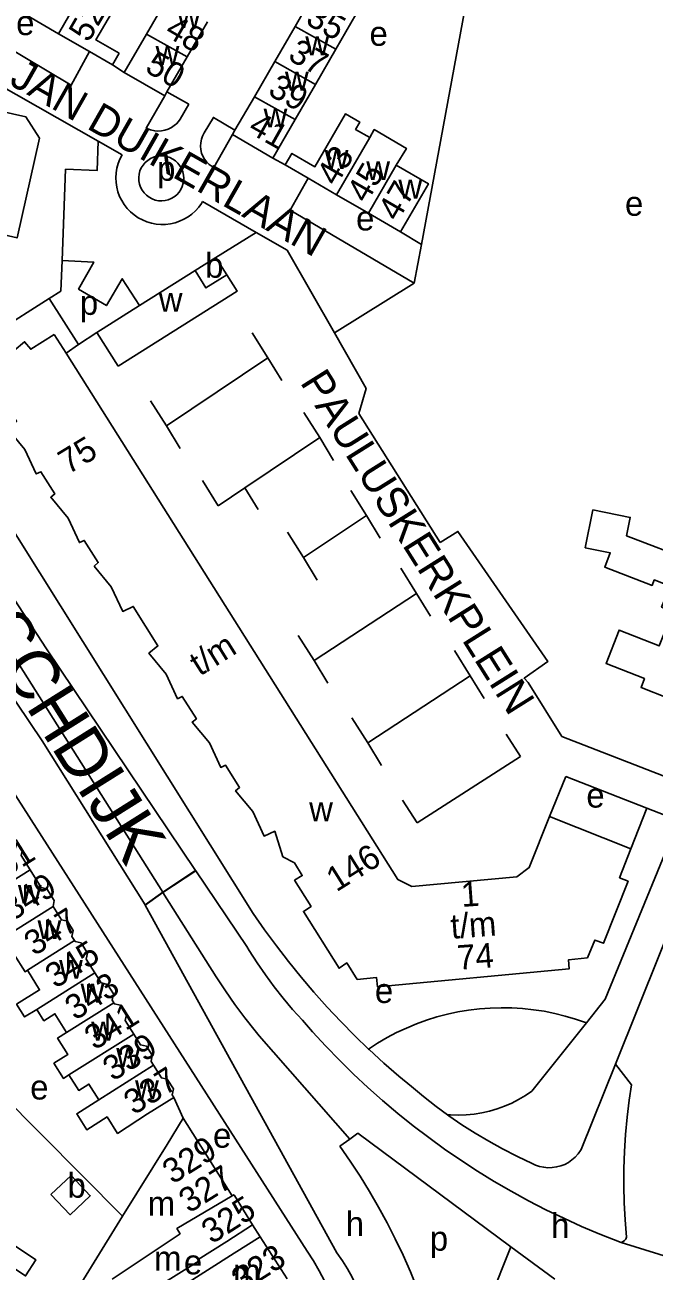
# Model space of a CAD drawing. Extents: x 159294 to 161936, y 384538 to 386517.
# Drawn here: x 160269 to 160371.2, y 384817.5 to 385020 of the extents above; entities that cross this region are included whole.
import ezdxf

# ---------------------------------------------------------------- set-up
doc = ezdxf.new("R2010")
doc.units = 0
for name, color, linetype in [('BLT_Basislijn', 7, 'Continuous'), ('BLT_Bebouwing', 7, 'Continuous'), ('BLT_Centroide', 7, 'Continuous'), ('BLT_Huisnummer', 7, 'Continuous'), ('BLT_Huisnummer_ tussenligend', 7, 'Continuous'), ('BLT_Huisnummer_reeks', 7, 'Continuous'), ('BLT_Onderverdeling_panden', 7, 'Continuous'), ('BLT_Straatnaam', 7, 'Continuous'), ('BLT_Straatnaam_hoofdweg', 7, 'Continuous'), ('BLT_Vlakafsluiter', 7, 'Continuous')]:
    doc.layers.add(name, color=color, linetype=linetype)

msp = doc.modelspace()

# ---------------------------------------------------------------- linework, layer by layer
at = {"layer": 'BLT_Basislijn'}
for p, q in [((160341.25, 385026.66), (160333.43, 384984.3)), ((160280.91, 385001.11), (160257.3, 385014.58)), ((160283.25, 385013.53), (160285.16, 385012.29)), ((160291.73, 385008.49), (160288.71, 385003.24)), ((160292.09, 385009.11), (160295.65, 385007.12)), ((160295.65, 385007.12), (160294.23, 385004.67)), ((160302.75, 385002.2), (160299.69, 384996.83)), ((160284.8, 384998.89), (160280.91, 385001.11)), ((160311.31, 384997.24), (160309.3, 384998.34)), ((160297.9, 384991.3), (160306.57, 384986.29)), ((160300.06, 384982.22), (160306.57, 384986.29)), ((160306.57, 384986.29), (160311.62, 384983.38)), ((160330.06, 384986.36), (160333.43, 384984.3)), ((160311.62, 384983.38), (160319.31, 384969.96)), ((160333.43, 384984.3), (160332.27, 384978.05)), ((160332.27, 384978.05), (160319.31, 384969.96)), ((160272.95, 384975.52), (160251.85, 384962.2)), ((160272.95, 384975.52), (160277.71, 384968.07)), ((160280.7, 384970.01), (160277.71, 384968.07)), ((160305.94, 384969.98), (160308.5, 384965.9)), ((160277.71, 384968.07), (160275.72, 384966.65)), ((160292, 384954.84), (160308.5, 384965.9)), ((160308.5, 384965.9), (160310.74, 384962.21)), ((160306.11, 384875.6), (160251.85, 384962.2)), ((160289.44, 384958.93), (160292, 384954.84)), ((160314.35, 384957), (160316.91, 384952.92)), ((160336.47, 384935.87), (160323.29, 384956.87)), ((160292, 384954.84), (160294.24, 384951.15)), ((160304.74, 384944.76), (160316.91, 384952.92)), ((160316.91, 384952.92), (160319.15, 384949.23)), ((160297.85, 384945.95), (160300.41, 384941.86)), ((160300.41, 384941.86), (160304.74, 384944.76)), ((160304.74, 384944.76), (160306.9, 384941.22)), ((160321.95, 384944.34), (160324.52, 384940.26)), ((160314.27, 384933.44), (160324.52, 384940.26)), ((160324.52, 384940.26), (160326.76, 384936.57)), ((160311.7, 384937.53), (160314.27, 384933.44)), ((160314.27, 384933.44), (160316.51, 384929.76)), ((160330.09, 384931.68), (160332.65, 384927.59)), ((160315.99, 384916.69), (160332.65, 384927.59)), ((160332.65, 384927.59), (160334.89, 384923.9)), ((160313.43, 384920.78), (160315.99, 384916.69)), ((160266.83, 384917.98), (160291.41, 384879.02)), ((160315.99, 384916.69), (160318.24, 384913.01)), ((160338.82, 384918.3), (160341.38, 384914.21)), ((160324.72, 384903.31), (160341.38, 384914.21)), ((160341.38, 384914.21), (160343.62, 384910.52)), ((160356.27, 384904.35), (160350.76, 384913.11)), ((160322.16, 384907.4), (160324.72, 384903.31)), ((160260.57, 384905.54), (160314.88, 384820.71)), ((160347.2, 384904.75), (160349.55, 384901.07)), ((160356.27, 384904.35), (160373.69, 384897.57)), ((160324.72, 384903.31), (160326.97, 384899.62)), ((160332.73, 384890.33), (160349.55, 384901.07)), ((160354.25, 384891.33), (160356.88, 384897.86)), ((160370.03, 384892.72), (160356.88, 384897.86)), ((160330.38, 384894.01), (160332.73, 384890.33)), ((160367.44, 384886.09), (160370.03, 384892.72)), ((160375.22, 384890.69), (160370.03, 384892.72)), ((160363.31, 384861.65), (160375.22, 384890.69)), ((160364.96, 384851.1), (160380.05, 384888.81)), ((160305.07, 384870.21), (160296.79, 384882.51)), ((160291.41, 384879.02), (160291.44, 384878.98)), ((160300.12, 384865.26), (160291.44, 384878.98)), ((160319.7, 384820.42), (160288.58, 384876.95)), ((160360.23, 384857.8), (160363.31, 384861.65)), ((160351.39, 384846.7), (160360.23, 384857.8)), ((160307.06, 384855.7), (160321.82, 384838.92)), ((160359.4, 384837.21), (160364.96, 384851.1)), ((160367.56, 384847.72), (160364.96, 384851.1)), ((160293.19, 384845.67), (160294.74, 384842.3)), ((160321.82, 384838.92), (160323.11, 384839.87)), ((160347.95, 384821.42), (160323.11, 384839.87)), ((160320.2, 384837.74), (160321.82, 384838.92)), ((160349.16, 384836), (160351.34, 384834.97)), ((160307.25, 384823.03), (160306.02, 384824.96)), ((160340.25, 384802.05), (160347.95, 384821.42)), ((160355.09, 384816.13), (160347.95, 384821.42))]:
    msp.add_line(p, q, dxfattribs=at)
for points in [[(160169.35, 385059.37), (160171.25, 385060.52), (160174.16, 385057.66), (160190.75, 385031.46), (160212.88, 384996.72), (160224.1, 384978.45), (160234.05, 384962.08), (160257.3, 384925.15), (160271.83, 384903.65), (160288.55, 384876.99)], [(160296.76, 384882.55), (160272.55, 384918.59), (160254.52, 384946.2), (160219.9, 385000), (160208.49, 385023.25)], [(160279.53, 385015.66), (160276.53, 385010.22), (160261.44, 385019.19)], [(160294.23, 385004.67), (160293.95, 385004.28), (160293.63, 385003.92), (160293.27, 385003.63), (160292.85, 385003.34), (160292.31, 385003.07), (160291.78, 385002.88), (160291.21, 385002.78), (160290.61, 385002.73), (160290.11, 385002.77), (160289.41, 385002.93), (160288.97, 385003.11), (160288.71, 385003.24)], [(160303.14, 385002.88), (160299.65, 385004.97), (160298.13, 385002.44)], [(160298.13, 385002.44), (160297.87, 385001.94), (160297.69, 385001.41), (160297.58, 385000.85), (160297.55, 385000.29), (160297.6, 384999.73), (160297.73, 384999.18), (160297.94, 384998.65), (160298.21, 384998.16), (160298.56, 384997.71), (160298.96, 384997.32), (160299.42, 384996.99), (160299.69, 384996.83)], [(160280.91, 385001.11), (160280.76, 384996.32), (160275.63, 384996.54), (160275.05, 384981.72)], [(160284.8, 384998.89), (160284.44, 384998.2), (160284.17, 384997.47), (160283.96, 384996.72), (160283.84, 384995.95), (160283.8, 384995.17), (160283.83, 384994.4), (160283.95, 384993.63), (160284.14, 384992.87), (160284.41, 384992.14), (160284.75, 384991.44), (160285.16, 384990.79), (160285.64, 384990.17), (160286.18, 384989.61), (160286.78, 384989.11), (160287.42, 384988.67), (160288.1, 384988.3), (160288.82, 384988), (160289.57, 384987.77), (160290.33, 384987.63), (160291.11, 384987.56), (160291.88, 384987.57), (160292.65, 384987.67), (160293.42, 384987.84), (160294.15, 384988.08), (160294.86, 384988.41), (160295.53, 384988.8), (160296.16, 384989.26), (160296.74, 384989.78), (160297.26, 384990.36), (160297.71, 384990.99), (160297.9, 384991.3)], [(160294.84, 384995.07), (160294.8, 384995.6), (160294.68, 384996.13), (160294.48, 384996.64), (160294.21, 384997.11), (160293.88, 384997.53), (160293.49, 384997.9), (160293.04, 384998.21), (160292.56, 384998.45), (160292.05, 384998.62), (160291.51, 384998.71), (160290.97, 384998.72), (160290.43, 384998.65), (160289.92, 384998.5), (160289.42, 384998.28), (160288.97, 384997.98), (160288.56, 384997.63), (160288.21, 384997.21), (160287.93, 384996.75), (160287.72, 384996.26), (160287.58, 384995.73), (160287.52, 384995.2), (160287.54, 384994.66), (160287.64, 384994.12), (160287.82, 384993.61), (160288.07, 384993.14), (160288.39, 384992.7), (160288.76, 384992.31), (160289.2, 384991.99), (160289.67, 384991.73), (160290.18, 384991.54), (160290.71, 384991.43), (160291.25, 384991.41), (160291.79, 384991.46), (160292.31, 384991.59), (160292.81, 384991.79), (160293.28, 384992.07), (160293.7, 384992.41), (160294.06, 384992.81), (160294.36, 384993.26), (160294.59, 384993.75), (160294.75, 384994.27), (160294.83, 384994.8), (160294.84, 384995.07)], [(160315.03, 384995.08), (160312.12, 384989.88), (160332.27, 384978.05)], [(160275.05, 384981.72), (160274.86, 384976.73), (160272.95, 384975.52)], [(160275.05, 384981.72), (160280.22, 384981.46), (160277.73, 384977.06), (160282.26, 384974.39), (160284.85, 384978.74), (160287.65, 384974.4)], [(160319.31, 384969.96), (160324.48, 384960.92), (160323.29, 384956.87)], [(160336.47, 384935.87), (160339.38, 384937.69), (160353.96, 384916.53), (160350.11, 384913.81), (160350.76, 384913.11)], [(160296.79, 384882.51), (160296.76, 384882.55)], [(160288.55, 384876.99), (160288.58, 384876.95)], [(160306.11, 384875.6), (160307.96, 384872.94), (160309.87, 384870.32), (160311.84, 384867.76), (160313.88, 384865.24), (160315.98, 384862.78), (160318.14, 384860.36), (160320.36, 384858), (160322.63, 384855.7), (160324.86, 384853.55)], [(160314.1, 384858.23), (160312.5, 384859.99), (160310.97, 384861.8), (160309.5, 384863.67), (160308.09, 384865.58), (160306.75, 384867.54), (160305.48, 384869.54), (160305.07, 384870.21)], [(160284.89, 384826.37), (160258.47, 384853), (160249.23, 384869.23)], [(160300.12, 384865.26), (160301.6, 384862.99), (160303.14, 384860.78), (160304.75, 384858.6), (160306.42, 384856.48), (160307.06, 384855.7)], [(160324.86, 384853.55), (160326.33, 384854.51), (160327.85, 384855.4), (160329.41, 384856.22), (160331, 384856.96), (160332.62, 384857.64), (160334.28, 384858.24), (160335.96, 384858.76), (160337.66, 384859.21), (160339.38, 384859.58), (160341.11, 384859.87), (160342.86, 384860.08), (160344.61, 384860.21), (160346.37, 384860.27), (160348.12, 384860.24), (160349.88, 384860.13), (160351.63, 384859.94), (160353.37, 384859.68), (160355.09, 384859.33), (160356.8, 384858.91), (160358.48, 384858.41), (160360.23, 384857.8)], [(160365.91, 384822.11), (160362.41, 384823.45), (160359.46, 384824.7), (160356.55, 384826.03), (160353.67, 384827.42), (160350.83, 384828.89), (160348.02, 384830.43), (160345.26, 384832.04), (160342.53, 384833.72), (160339.85, 384835.46), (160337.21, 384837.27), (160334.62, 384839.15), (160332.08, 384841.09), (160329.59, 384843.09), (160327.14, 384845.16), (160324.75, 384847.28), (160322.41, 384849.47), (160320.13, 384851.71), (160317.9, 384854.01), (160315.74, 384856.36), (160314.1, 384858.23)], [(160324.86, 384853.55), (160324.96, 384853.45), (160327.35, 384851.27), (160329.79, 384849.14), (160331.8, 384847.46)], [(160366.78, 384822.99), (160366.55, 384825.76), (160366.4, 384828.54), (160366.33, 384831.33), (160366.34, 384834.11), (160366.43, 384836.9), (160366.61, 384839.68), (160366.86, 384842.45), (160367.19, 384845.22), (160367.56, 384847.72)], [(160331.8, 384847.46), (160333.78, 384845.81), (160335.81, 384844.23), (160337.67, 384842.86)], [(160351.39, 384846.7), (160350.33, 384845.98), (160349.23, 384845.33), (160348.1, 384844.75), (160346.92, 384844.24), (160345.72, 384843.8), (160344.49, 384843.45), (160343.25, 384843.16), (160341.98, 384842.96), (160340.71, 384842.84), (160339.43, 384842.79), (160338.16, 384842.83), (160337.67, 384842.86)], [(160337.67, 384842.86), (160337.88, 384842.71), (160340.01, 384841.25), (160342.17, 384839.87), (160344.38, 384838.55), (160346.63, 384837.3), (160348.92, 384836.11), (160349.16, 384836)], [(160320.2, 384837.74), (160321.87, 384835.33), (160323.47, 384832.88), (160325.01, 384830.39), (160326.48, 384827.86), (160327.87, 384825.29), (160329.2, 384822.68), (160330.45, 384820.04), (160331.64, 384817.36), (160332.74, 384814.65), (160333.78, 384811.91), (160334.74, 384809.15), (160335.62, 384806.36), (160336.43, 384803.55), (160337.17, 384800.64)], [(160351.34, 384834.97), (160351.97, 384834.68), (160352.63, 384834.46), (160353.31, 384834.32), (160354, 384834.26), (160354.7, 384834.28), (160355.39, 384834.38), (160356.06, 384834.55), (160356.71, 384834.8), (160357.33, 384835.13), (160357.9, 384835.52), (160358.43, 384835.98), (160358.9, 384836.49), (160359.3, 384837.06), (160359.4, 384837.21)], [(160365.91, 384822.11), (160366.21, 384822.27), (160366.45, 384822.42), (160366.63, 384822.63), (160366.78, 384822.99)], [(160314.88, 384820.71), (160315.89, 384819.13), (160316.84, 384817.51), (160317.71, 384815.85), (160318.52, 384814.15), (160319.25, 384812.42), (160319.5, 384811.75)], [(160319.7, 384820.42), (160320.6, 384819.14), (160321.44, 384817.81), (160322.21, 384816.44), (160322.91, 384815.03), (160323.53, 384813.59), (160324.08, 384812.12), (160324.56, 384810.63), (160324.96, 384809.11), (160325.28, 384807.57), (160325.46, 384806.48)]]:
    msp.add_lwpolyline(points, dxfattribs=at)
at = {"layer": 'BLT_Bebouwing'}
for p, q in [((160292.08, 385024.23), (160288.77, 385018.52)), ((160312.91, 385019.77), (160316.23, 385025.5)), ((160274.49, 385018.58), (160269.4, 385021.52)), ((160295.38, 385014.79), (160298.7, 385020.5)), ((160309.61, 385014.06), (160312.91, 385019.77)), ((160279.53, 385015.66), (160274.49, 385018.58)), ((160288.77, 385018.52), (160285.16, 385012.29)), ((160283.25, 385013.53), (160279.53, 385015.66)), ((160319.53, 385016.04), (160316.23, 385010.33)), ((160284.33, 385015.42), (160283.25, 385013.53)), ((160292.09, 385009.11), (160295.38, 385014.79)), ((160306.3, 385008.34), (160309.61, 385014.06)), ((160285.16, 385012.29), (160291.73, 385008.49)), ((160316.23, 385010.33), (160312.93, 385004.61)), ((160291.73, 385008.49), (160292.09, 385009.11)), ((160303.14, 385002.88), (160306.3, 385008.34)), ((160312.93, 385004.61), (160309.3, 384998.34)), ((160302.75, 385002.2), (160303.14, 385002.88)), ((160309.3, 384998.34), (160302.75, 385002.2)), ((160324.83, 384989.39), (160319.64, 384992.41)), ((160330.06, 384986.36), (160324.83, 384989.39)), ((160300.06, 384982.22), (160296.68, 384980.09)), ((160296.68, 384980.09), (160287.65, 384974.4)), ((160287.65, 384974.4), (160280.7, 384970.01)), ((160273.8, 384969.7), (160275.72, 384966.65)), ((160280.7, 384970.01), (160284.16, 384964.53)), ((160302.68, 384829.66), (160294.74, 384842.3)), ((160306.02, 384824.96), (160303.06, 384829.73)), ((160311.62, 384816.18), (160307.25, 384823.03))]:
    msp.add_line(p, q, dxfattribs=at)
for points in [[(160316.23, 385025.5), (160322.8, 385021.69), (160319.53, 385016.04)], [(160284.01, 385023.49), (160280.57, 385017.57), (160284.33, 385015.42)], [(160256.15, 385008.01), (160269.2, 385005.06), (160271.4, 385001.59), (160267.76, 384985.37), (160256.91, 384987.87), (160254.38, 384986.26), (160252.79, 384988.76), (160248.74, 384989.69), (160249.62, 384993.76), (160248.08, 384996.27), (160250.56, 384997.86), (160252.61, 385006.91)], [(160319.53, 385002.84), (160321.09, 385005.55), (160323.43, 385004.21), (160322.75, 385003.03), (160325.04, 385001.73)], [(160311.31, 384997.24), (160312.4, 384999.12), (160316.14, 384996.95), (160319.53, 385002.84)], [(160325.04, 385001.73), (160325.77, 385002.99), (160331.01, 384999.93), (160329.34, 384997.19)], [(160315.03, 384995.08), (160311.31, 384997.24)], [(160329.34, 384997.19), (160334.57, 384994.18), (160330.06, 384986.36)], [(160319.64, 384992.41), (160315.03, 384995.08)], [(160301.83, 384979.38), (160300.06, 384982.22)], [(160284.16, 384964.53), (160303.48, 384976.72), (160301.83, 384979.38)], [(160280.26, 384932.05), (160280.93, 384932.61), (160278.66, 384936.21), (160278.26, 384936.03), (160277.87, 384935.86), (160276.03, 384939.85), (160273.22, 384943.23), (160273.88, 384943.78), (160271.63, 384947.39), (160270.86, 384947.02), (160269.01, 384951.01), (160266.22, 384954.39), (160267.68, 384955.59), (160262.97, 384963.02), (160264.2, 384963.79), (160263.84, 384964.25), (160268.96, 384968.51), (160269.96, 384967.3), (160273.8, 384969.7)], [(160275.72, 384966.65), (160329.61, 384881.08), (160331.89, 384879.95), (160348.95, 384881.56), (160350.96, 384883.05), (160354.25, 384891.33)], [(160386.76, 384930.42), (160382.12, 384932.29), (160377.98, 384933.95), (160377.52, 384932.82), (160366.75, 384936.98), (160367.35, 384939.95), (160361.29, 384941.17), (160360.05, 384935.03), (160364.11, 384934.21), (160363.21, 384931.88), (160370.91, 384928.91), (160371.25, 384929.79), (160373.83, 384928.79), (160372.46, 384925.38), (160378.38, 384923), (160383.02, 384921.14)], [(160306.03, 384892.16), (160303.24, 384895.54), (160303.89, 384896.08), (160301.62, 384899.68), (160300.84, 384899.32), (160299.01, 384903.32), (160296.2, 384906.7), (160296.88, 384907.23), (160294.59, 384910.85), (160293.82, 384910.49), (160291.98, 384914.49), (160289.18, 384917.88), (160290.64, 384919.08), (160286.62, 384925.48), (160284.91, 384924.68), (160283.05, 384928.67), (160280.26, 384932.05)], [(160382.04, 384918.62), (160377.38, 384920.45), (160373.25, 384922.07), (160372.07, 384919.07), (160365.56, 384921.63), (160363.43, 384916.2), (160369.67, 384913.75), (160369.11, 384912.33), (160373.51, 384910.58), (160378.15, 384908.73)], [(160360.44, 384868.35), (160357.31, 384868.04), (160357.43, 384866.56), (160326.3, 384863.66), (160326.15, 384865.15), (160323.02, 384864.86), (160321.31, 384867.55), (160320.05, 384866.69), (160314.26, 384875.92), (160315.52, 384876.72), (160312.83, 384880.99), (160314.07, 384881.75), (160312.83, 384883.81), (160310.93, 384884.79), (160309.6, 384888.95), (160307.88, 384888.16), (160306.03, 384892.16)], [(160354.25, 384891.33), (160367.44, 384886.09)], [(160269.86, 384882.68), (160268.41, 384884.99), (160268.62, 384885.91), (160267.59, 384887.54), (160266.56, 384887.78)], [(160367.44, 384886.09), (160365.62, 384881.38), (160367, 384880.83), (160363.01, 384870.73), (160361.62, 384871.26), (160360.44, 384868.35)], [(160273.6, 384876.69), (160273.79, 384877.7), (160272.6, 384879.59), (160271.68, 384879.8), (160269.86, 384882.68)], [(160277.08, 384871.17), (160276.65, 384871.86), (160276.87, 384872.83), (160275.93, 384874.32), (160274.95, 384874.54), (160273.6, 384876.69)], [(160269.46, 384866.37), (160269.05, 384866.12), (160267.3, 384868.93), (160264.19, 384866.97), (160263.22, 384868.52), (160261.09, 384867.17), (160260.35, 384868.35), (160265.59, 384871.65)], [(160280.37, 384865.93), (160278.97, 384868.15), (160279.19, 384869.11), (160278.14, 384870.79), (160277.19, 384871), (160277.08, 384871.17)], [(160270.94, 384859.99), (160268.97, 384858.76), (160267.68, 384860.82), (160271.4, 384863.16), (160269.46, 384866.37)], [(160283.45, 384861.07), (160283.18, 384861.49), (160283.42, 384862.51), (160282.43, 384864.06), (160281.4, 384864.3), (160280.37, 384865.93)], [(160275.8, 384856.25), (160273.89, 384859.28), (160272.1, 384858.15), (160270.94, 384859.99)], [(160286.7, 384855.96), (160285.31, 384858.16), (160285.53, 384859.13), (160284.57, 384860.67), (160283.55, 384860.9), (160283.45, 384861.07)], [(160276.18, 384849.33), (160275.28, 384848.76), (160273.73, 384851.23), (160275.99, 384852.65), (160274.32, 384855.32), (160275.8, 384856.25)], [(160289.92, 384850.9), (160289.53, 384851.52), (160289.7, 384852.54), (160288.79, 384853.99), (160287.8, 384854.21), (160286.7, 384855.96)], [(160293.19, 384845.67), (160292.93, 384846.09), (160293.15, 384847.06), (160292.15, 384848.65), (160291.21, 384848.86), (160289.92, 384850.9)], [(160281.03, 384845.29), (160279.42, 384847.86), (160277.76, 384846.82), (160276.18, 384849.33)], [(160293.19, 384845.67), (160288.96, 384843.01), (160284.07, 384839.83), (160282.38, 384842.5), (160279.08, 384840.42), (160277.44, 384843.03), (160281.03, 384845.29)], [(160294.74, 384842.3), (160292.12, 384838.04), (160284.89, 384826.37)], [(160303.06, 384829.73), (160302.98, 384829.85), (160302.68, 384829.66)], [(160275.23, 384810.74), (160284.89, 384826.37)], [(160266.14, 384815.55), (160267.55, 384817.71), (160269.13, 384816.68), (160270.82, 384819.28), (160266.35, 384822.25), (160261.94, 384825.06)], [(160286.03, 384810.67), (160285.23, 384811.6), (160297.31, 384819.13), (160297.18, 384819.33), (160301.8, 384822.27), (160306.02, 384824.96)], [(160307.25, 384823.03), (160303.03, 384820.35), (160290, 384812.07), (160291.57, 384809.6), (160290.56, 384808.96), (160291.29, 384807.81), (160296.61, 384811.19), (160298.69, 384807.92)]]:
    msp.add_lwpolyline(points, dxfattribs=at)
msp.add_lwpolyline([(160273.24, 384829.88), (160276.52, 384832.99), (160279.63, 384829.71), (160276.35, 384826.6)], close=True, dxfattribs=at)
at = {"layer": 'BLT_Onderverdeling_panden'}
for p, q in [((160274.49, 385018.58), (160278.98, 385026.41)), ((160312.91, 385019.77), (160319.53, 385016.04)), ((160288.77, 385018.52), (160295.38, 385014.79)), ((160309.61, 385014.06), (160316.23, 385010.33)), ((160306.3, 385008.34), (160312.93, 385004.61)), ((160325.04, 385001.73), (160319.64, 384992.41)), ((160329.34, 384997.19), (160324.83, 384989.39)), ((160261.81, 384877.61), (160269.86, 384882.68)), ((160265.59, 384871.65), (160273.6, 384876.69)), ((160269.46, 384866.37), (160277.08, 384871.17)), ((160270.94, 384859.99), (160280.37, 384865.93)), ((160275.8, 384856.25), (160283.45, 384861.07)), ((160276.18, 384849.33), (160286.7, 384855.96)), ((160281.03, 384845.29), (160289.92, 384850.9))]:
    msp.add_line(p, q, dxfattribs=at)
for points in [[(160296.68, 384980.09), (160298.43, 384977.26), (160301.83, 384979.38)], [(160302.68, 384829.66), (160293.71, 384824.36), (160294.23, 384823.53), (160283.18, 384816.13)]]:
    msp.add_lwpolyline(points, dxfattribs=at)
at = {"layer": 'BLT_Vlakafsluiter'}
for p, q in [((160291.41, 384879.02), (160296.76, 384882.55)), ((160291.44, 384878.98), (160296.79, 384882.51)), ((160291.41, 384879.02), (160288.55, 384876.99)), ((160291.44, 384878.98), (160288.58, 384876.95)), ((160365.91, 384822.11), (160378.54, 384818.13))]:
    msp.add_line(p, q, dxfattribs=at)

# ---------------------------------------------------------------- texts
at = {"layer": 'BLT_Centroide'}
for s, p in [('w', (160293.73, 385019.5)), ('e', (160267.6, 385018.35)), ('e', (160325, 385016.61)), ('w', (160314.58, 385015.06)), ('w', (160290.25, 385013.5)), ('w', (160311.27, 385009.34)), ('w', (160307.8, 385003.34)), ('w', (160317.72, 384996.61)), ('p', (160290.5, 384994.67)), ('w', (160324.48, 384994.78)), ('w', (160329.7, 384991.77)), ('e', (160366.51, 384988.98)), ('e', (160322.82, 384986.59)), ('b', (160298.3, 384978.91)), ('p', (160277.95, 384972.88)), ('w', (160290.77, 384973.38)), ('e', (160360.23, 384892.79)), ('w', (160315.2, 384890.58)), ('w', (160267.88, 384877.16)), ('w', (160271.07, 384871.41)), ('w', (160274.57, 384864.97)), ('w', (160278.06, 384861.09)), ('e', (160325.88, 384861.03)), ('w', (160279.8, 384854.91)), ('w', (160283.86, 384850.62)), ('e', (160269.88, 384845.34)), ('w', (160286.92, 384845.38)), ('e', (160299.58, 384837.51)), ('b', (160275.94, 384829.39)), ('m', (160288.97, 384826.45)), ('h', (160321.14, 384823.14)), ('h', (160354.51, 384822.85)), ('p', (160334.8, 384820.77)), ('m', (160290.01, 384817.53)), ('e', (160294.86, 384816.92)), ('m', (160302.86, 384815.41))]:
    msp.add_text(s, height=4, dxfattribs=at).set_placement(p)
at = {"layer": 'BLT_Huisnummer'}
for s, rotation, p in [('52', 59.9053, (160279.37, 385017.01)), ('35', 330.5972, (160314.42, 385020.26)), ('50', 329.9026, (160288.33, 385012.52)), ('41', 330.5972, (160305.09, 385002.61)), ('43', 59.8966, (160319.62, 384993.65)), ('47', 59.8966, (160329.59, 384987.89)), ('349', 32.2119, (160266.96, 384874.24)), ('345', 32.2119, (160273.96, 384863.29)), ('341', 32.2119, (160280.34, 384853.27)), ('337', 32.2119, (160286.72, 384842.73)), ('325', 32.5742, (160299.37, 384821.75)), ('323', 32.4656, (160304.23, 384813.89))]:
    msp.add_text(s, height=4, rotation=rotation, dxfattribs=at).set_placement(p)
at = {"layer": 'BLT_Huisnummer_ tussenligend'}
for s, rotation, p in [('48', 329.9026, (160291.55, 385018.36)), ('37', 330.5972, (160311.55, 385014.47)), ('39', 330.5972, (160308.3, 385008.75)), ('45', 59.8966, (160324.53, 384990.86)), ('351', 32.2119, (160263.47, 384879.79)), ('347', 32.2119, (160270.53, 384868.58)), ('343', 32.2119, (160277.17, 384858.1)), ('339', 32.2119, (160283.31, 384848.21))]:
    msp.add_text(s, height=4, rotation=rotation, dxfattribs=at).set_placement(p)
at = {"layer": 'BLT_Huisnummer_reeks'}
for s, rotation, p in [('75', 31.1691, (160276.03, 384946.86)), ('t/m', 32.109, (160297.42, 384914.07)), ('146', 32.109, (160319.62, 384878.99)), ('1', 4.2231, (160340, 384876.63)), ('t/m', 4.2231, (160338.32, 384871.46)), ('74', 4.2231, (160339.38, 384866.4)), ('329', 32.1242, (160293, 384831.48)), ('327', 32.1242, (160295.67, 384826.76))]:
    msp.add_text(s, height=4, rotation=rotation, dxfattribs=at).set_placement(p)
at = {"layer": 'BLT_Straatnaam'}
for s, rotation, p in [('JAN DUIKERLAAN', 330.4227, (160266.28, 385010.42)), ('PAULUSKERKPLEIN', 302.141, (160313.63, 384961.91))]:
    msp.add_text(s, height=5, rotation=rotation, dxfattribs=at).set_placement(p)
at = {"layer": 'BLT_Straatnaam_hoofdweg'}
msp.add_text('BOSCHDIJK', height=8, rotation=302.141, dxfattribs=at).set_placement((160252.97, 384934.84))

doc.saveas('drawing.dxf')
